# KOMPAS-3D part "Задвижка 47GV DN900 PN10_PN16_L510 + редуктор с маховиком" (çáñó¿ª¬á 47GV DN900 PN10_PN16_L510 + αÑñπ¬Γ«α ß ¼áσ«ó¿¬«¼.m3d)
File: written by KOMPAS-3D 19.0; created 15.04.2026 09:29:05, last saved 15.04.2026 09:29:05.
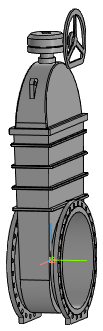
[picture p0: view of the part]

Document properties: Автор: Энергия; Полное имя файла: ..\..\Задвижка 47GV DN900 PN10_PN16_L510 + редуктор с маховиком.a3d

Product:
- Part/product: Задвижка 47GV DN900 PN10_PN16_L510 + редуктор с маховиком
    Масса: 4248.18

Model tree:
1. Операция без истории:1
